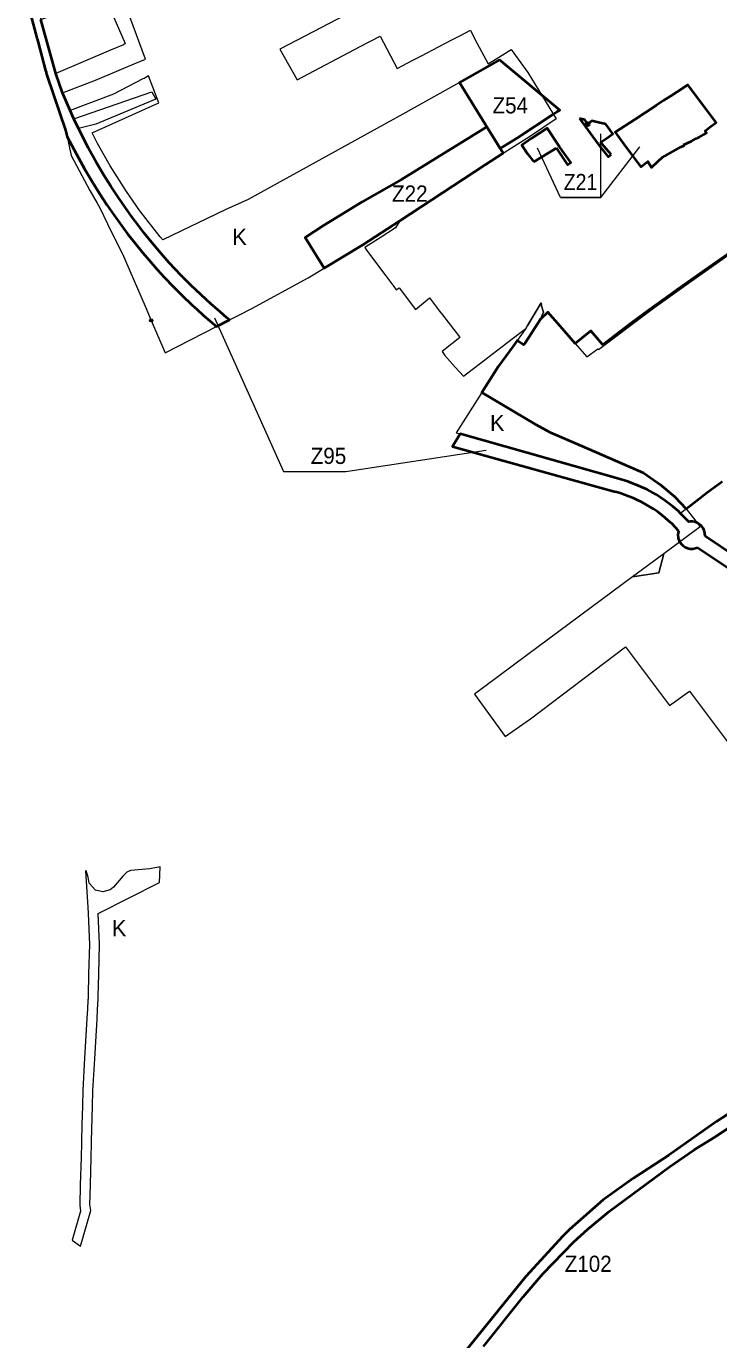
# Model space of a CAD drawing. Extents: x -650276 to -642489, y -1074425 to -1066658.
# Drawn here: x -649069 to -648043, y -1072629 to -1070685 of the extents above; entities that cross this region are included whole.
import ezdxf

# ---------------------------------------------------------------- set-up
doc = ezdxf.new("R2010")
doc.units = 0
doc.header["$LTSCALE"] = 9.6
doc.header["$PDMODE"] = 32
doc.header["$PDSIZE"] = 4.8
for name, color, linetype, lineweight in [('1', 7, 'Continuous', 13), ('42', 7, 'Continuous', 25), ('43', 7, 'Continuous', 13), ('44', 7, 'Continuous', 40), ('45', 7, 'Continuous', 40), ('46', 7, 'Continuous', 13), ('47', 7, 'Continuous', 13)]:
    doc.layers.add(name, color=color, linetype=linetype, lineweight=lineweight)

msp = doc.modelspace()

# ---------------------------------------------------------------- linework, layer by layer
at = {"layer": '1'}
for points in [[(-648597.74, -1070668.62), (-648643.953, -1070692.685), (-648693.45, -1070718.46), (-648667.72, -1070764.15), (-648574.27, -1070714.5), (-648544.862, -1070699.429), (-648519.58, -1070747.4)], [(-648519.58, -1070747.4), (-648496.18, -1070734.81), (-648484.68, -1070728.83), (-648474.03, -1070723.29), (-648466.94, -1070719.6), (-648449.19, -1070710.37), (-648438.55, -1070704.83), (-648427.9, -1070699.29), (-648410.84, -1070690.42), (-648404.45, -1070703.55), (-648384.89, -1070740.06), (-648363.96, -1070727.29), (-648350.805, -1070719.256), (-648326.033, -1070753.12), (-648309.833, -1070779.597), (-648284.021, -1070821.784), (-648322.17, -1070847.2), (-648389.33, -1070889.79), (-648515.46, -1070972.94), (-648522.01, -1070983.2), (-648543.48, -1070996.94), (-648567.23, -1071012.14), (-648564.89, -1071016.27), (-648536.41, -1071054.13), (-648524.53, -1071069.93), (-648520.86, -1071075.05), (-648516.83, -1071072.11), (-648492.65, -1071103.8), (-648475.37, -1071089.83), (-648471.64, -1071086.81), (-648456.65, -1071106.41), (-648452.32, -1071112.08), (-648427.47, -1071144.54), (-648426.82, -1071145.4), (-648452.84, -1071166.32), (-648448.82, -1071172.06), (-648433.9, -1071189.43), (-648421.16, -1071202.66), (-648416.99, -1071199.46), (-648396.21, -1071183.48), (-648379.15, -1071170.37), (-648355.66, -1071152.35), (-648347.22, -1071145.94), (-648333.1, -1071135.21), (-648328.9, -1071132.02), (-648326.92, -1071128.68), (-648306.39, -1071093.99), (-648305.83, -1071096.48), (-648306.31, -1071097.36), (-648303.08, -1071108.16), (-648307.33, -1071118.47), (-648296.34, -1071108.04), (-648278.39, -1071128.74), (-648256.04, -1071154.5), (-648238.84, -1071174.33), (-648228.01, -1071166.19), (-648222.669, -1071162.121), (-648221.672, -1071163.248), (-648140.102, -1071102.285), (-648084.716, -1071062.607), (-648029.353, -1071023.703)], [(-648305.83, -1071096.48), (-648306.39, -1071093.99), (-648326.92, -1071128.68), (-648328.9, -1071132.02), (-648341.942, -1071150.072)], [(-648303.08, -1071108.16), (-648306.31, -1071097.36), (-648305.83, -1071096.48)], [(-648330.78, -1071154.36), (-648319.77, -1071137.52), (-648307.33, -1071118.47), (-648303.08, -1071108.16)], [(-648341.942, -1071150.072), (-648332.354, -1071156.279), (-648330.78, -1071154.36)], [(-648038.18, -1071358.51), (-648060.01, -1071374.69), (-648064.98, -1071378.51), (-648071.17, -1071383.26), (-648074.27, -1071385.62), (-648091.92, -1071399.07), (-648077.53, -1071417.4), (-648070.912, -1071425.883), (-648125, -1071465.96), (-648132.14, -1071493.74), (-648170.93, -1071500), (-648326.08, -1071615.1), (-648370.52, -1071648.07), (-648405.21, -1071673.54), (-648359.48, -1071736.12), (-648321.94, -1071710.22), (-648181.6, -1071603.39), (-648116.54, -1071690.46), (-648086.68, -1071669.2), (-648027.69, -1071748)]]:
    msp.add_lwpolyline(points, dxfattribs=at)
msp.add_lwpolyline([(-648132.14, -1071493.74), (-648125, -1071465.96), (-648170.93, -1071500)], close=True, dxfattribs=at)
at = {"layer": '42'}
msp.add_lwpolyline([(-648386.587, -1070833.807), (-648512.981, -1070911.776), (-648571.14, -1070944.67), (-648628.712, -1070979.892), (-648655.76, -1070997.5), (-648627.39, -1071042.65), (-648570.23, -1071008.2), (-648515.46, -1070972.94), (-648389.33, -1070889.79), (-648362.519, -1070872.788)], close=True, dxfattribs=at)
at = {"layer": '44'}
for points in [[(-649068.65, -1070642.23), (-649054.31, -1070696.44), (-649052.77, -1070702.25), (-649052.44, -1070703.48), (-649051.03, -1070708.74), (-649040.03, -1070750.06), (-649039.38, -1070752.51), (-649039.06, -1070753.72), (-649038.51, -1070755.38), (-649027.74, -1070787.51), (-649027.64, -1070787.8), (-649019.48, -1070812.18), (-649018.48, -1070815.18), (-649011.24, -1070836.79), (-649010.67, -1070838.5), (-649007.885, -1070848.153), (-648994.464, -1070873.974), (-648982.467, -1070895.704), (-648970.712, -1070915.663), (-648960.268, -1070932.429), (-648949.389, -1070949.031), (-648939.232, -1070963.818), (-648918.601, -1070991.969), (-648896.068, -1071020.184), (-648886.874, -1071031.044), (-648874.793, -1071044.773), (-648863.847, -1071056.723), (-648851.175, -1071069.886), (-648838.696, -1071082.562), (-648823.087, -1071097.562), (-648816.379, -1071103.782), (-648806.239, -1071112.938), (-648797, -1071121), (-648790.23, -1071126.818), (-648787.207, -1071129.363), (-648767.824, -1071119.455), (-648771.725, -1071116.233), (-648781.806, -1071107.721), (-648795.407, -1071095.8), (-648824.292, -1071068.677), (-648839.273, -1071053.556), (-648856.883, -1071034.761), (-648869.629, -1071020.411), (-648880.44, -1071007.703), (-648894.164, -1070990.806), (-648902.714, -1070979.812), (-648912.396, -1070966.893), (-648922.92, -1070952.242), (-648932.78, -1070937.887), (-648943.414, -1070921.659), (-648953.605, -1070905.299), (-648965.093, -1070885.794), (-648976.834, -1070864.527), (-648985.145, -1070848.538), (-648991.386, -1070835.954), (-648998.132, -1070821.723), (-649003.641, -1070809.566), (-649014.888, -1070782.994), (-649025.129, -1070754.377), (-649047.11, -1070674.743)], [(-648079.109, -1071418.563), (-648082.391, -1071418.063), (-648085.477, -1071418.086), (-648087.928, -1071418.446), (-648100.438, -1071405.517), (-648103.268, -1071402.88), (-648111.646, -1071395.618), (-648123.313, -1071386.696), (-648136.263, -1071378.194), (-648149.571, -1071370.788), (-648162.084, -1071364.918), (-648178.158, -1071358.781), (-648191.25, -1071354.858), (-648426.18, -1071288.32), (-648437.454, -1071306.778), (-648196.236, -1071374.226)], [(-648069.022, -1071424.443), (-648074.341, -1071420.189), (-648079.108, -1071418.564), (-648079.109, -1071418.563)], [(-648063.593, -1071439.723), (-648063.862, -1071435.078), (-648064.838, -1071431.28), (-648066.623, -1071427.592), (-648069.022, -1071424.443)], [(-648103.894, -1071436.836), (-648103.478, -1071442.736), (-648101.203, -1071448.31)], [(-648101.203, -1071448.31), (-648098.259, -1071452.196), (-648096.014, -1071454.192), (-648093.059, -1071456.066), (-648089.539, -1071457.489), (-648085.585, -1071458.248), (-648081.642, -1071458.215), (-648078.539, -1071457.636), (-648074.86, -1071456.248)], [(-648016.446, -1071471.268), (-648063.593, -1071439.723)], [(-648074.86, -1071456.248), (-648027.562, -1071487.894)], [(-647942.21, -1072238.54), (-648046.69, -1072306.3), (-648117.12, -1072356), (-648169.81, -1072390.035), (-648214.73, -1072422.41), (-648264.618, -1072466.244), (-648274.53, -1072476.196), (-648328.847, -1072535.816), (-648369.37, -1072585.645), (-648431.557, -1072662.77)], [(-648391.796, -1072639.344), (-648333.178, -1072565.837), (-648303.791, -1072531.792), (-648258.165, -1072484.283), (-648237.406, -1072465.811), (-648205.298, -1072439.308), (-648116.32, -1072373.44), (-648079.76, -1072348.46), (-648050.276, -1072330.025), (-647969.894, -1072276.479)]]:
    msp.add_lwpolyline(points, dxfattribs=at)
at = {"layer": '44', "lineweight": 13}
msp.add_lwpolyline([(-648790.074, -1071116.496), (-648687.825, -1071343.817), (-648595.588, -1071343.817), (-648387.63, -1071312.498)], dxfattribs=at)
at = {"layer": '44'}
for centre, radius, start, end in [((-648244.965, -1071557.871), 190, 41.59858, 75.1393), ((-648083.781, -1071438.172), 20.157, 161.35794, 176.20098)]:
    msp.add_arc(centre, radius, start, end, dxfattribs=at)
at = {"layer": '45'}
msp.add_lwpolyline([(-648368.163, -1070734.376), (-648427.25, -1070767.95), (-648366.98, -1070865.44), (-648341.58, -1070849.98), (-648287.74, -1070814.32), (-648282.44, -1070810.84), (-648278.832, -1070808.761)], close=True, dxfattribs=at)
for points in [[(-648095.42, -1070860.3), (-648083.65, -1070854.89), (-648076.73, -1070851.07), (-648074.41, -1070849.79), (-648072.59, -1070848.79), (-648065.35, -1070844.8), (-648061.52, -1070842.68), (-648063.76, -1070839.49), (-648056.61, -1070834.26), (-648047.17, -1070827.35), (-648089.27, -1070771.57), (-648104.78, -1070781.65), (-648114.77, -1070788.08), (-648125.2, -1070794.79), (-648136.08, -1070801.79)], [(-648095.42, -1070860.3), (-648083.65, -1070854.89), (-648076.73, -1070851.07), (-648074.41, -1070849.79), (-648072.59, -1070848.79), (-648065.35, -1070844.8), (-648061.52, -1070842.68), (-648063.76, -1070839.49), (-648056.61, -1070834.26), (-648047.17, -1070827.35), (-648089.27, -1070771.57), (-648104.78, -1070781.65), (-648114.77, -1070788.08), (-648125.2, -1070794.79), (-648136.08, -1070801.79)], [(-648136.08, -1070801.79), (-648151.77, -1070812.11), (-648167.6, -1070822.53), (-648196.65, -1070841.7), (-648181.75, -1070862.74), (-648158.58, -1070892.98), (-648148.34, -1070884.92), (-648142.79, -1070893.78), (-648133.14, -1070884.6), (-648127, -1070878.75), (-648122.72, -1070876.44), (-648111.24, -1070870.11), (-648099.85, -1070863.82), (-648094.9, -1070861.09), (-648095.42, -1070860.3)], [(-648136.08, -1070801.79), (-648151.77, -1070812.11), (-648167.6, -1070822.53), (-648196.65, -1070841.7), (-648181.75, -1070862.74), (-648158.58, -1070892.98), (-648148.34, -1070884.92), (-648142.79, -1070893.78), (-648133.14, -1070884.6), (-648127, -1070878.75), (-648122.72, -1070876.44), (-648111.24, -1070870.11), (-648099.85, -1070863.82), (-648094.9, -1070861.09), (-648095.42, -1070860.3)], [(-648237.46, -1070829.68), (-648241.96, -1070823.46), (-648249.5, -1070821.08)], [(-648249.5, -1070821.08), (-648222.158, -1070859.221), (-648217.1, -1070865.56), (-648207.151, -1070878.029), (-648202.798, -1070874.754)], [(-648210.517, -1070829.445), (-648221.58, -1070827.03), (-648231.22, -1070824.92), (-648237.46, -1070829.68)], [(-648218.11, -1070856.44), (-648209.37, -1070850.44), (-648200.17, -1070844.094), (-648210.517, -1070829.445)], [(-648386.587, -1070833.807), (-648512.981, -1070911.776), (-648571.14, -1070944.67), (-648628.712, -1070979.892), (-648655.76, -1070997.5), (-648627.39, -1071042.65), (-648570.23, -1071008.2), (-648515.46, -1070972.94), (-648389.33, -1070889.79)], [(-648386.587, -1070833.807), (-648512.981, -1070911.776), (-648571.14, -1070944.67), (-648628.712, -1070979.892), (-648655.76, -1070997.5), (-648627.39, -1071042.65), (-648570.23, -1071008.2), (-648515.46, -1070972.94), (-648389.33, -1070889.79)], [(-648389.33, -1070889.79), (-648362.519, -1070872.788), (-648386.587, -1070833.807)], [(-648389.33, -1070889.79), (-648362.519, -1070872.788), (-648386.587, -1070833.807)], [(-648284.02, -1070864.91), (-648267.24, -1070889.9), (-648262.4, -1070886.58), (-648279.39, -1070862.98), (-648297.39, -1070835.36), (-648320.02, -1070850.16), (-648335.19, -1070860.49), (-648326.41, -1070873.55), (-648317.14, -1070885.48)], [(-648317.14, -1070885.48), (-648285.72, -1070865.96), (-648284.02, -1070864.91)], [(-648202.798, -1070874.754), (-648212.94, -1070862.74), (-648217.85, -1070856.93), (-648218.11, -1070856.44)], [(-647913.45, -1070940.79), (-648062.53, -1071044.59), (-648102.55, -1071072.86), (-648125.53, -1071089.51), (-648141.12, -1071100.71), (-648155.77, -1071111.23), (-648172.48, -1071123.95), (-648197.57, -1071143.03), (-648215.08, -1071156.35), (-648232.8, -1071135.6), (-648245.49, -1071145.91), (-648256.04, -1071154.5), (-648278.39, -1071128.74), (-648296.34, -1071108.04), (-648307.33, -1071118.47), (-648319.77, -1071137.52), (-648330.78, -1071154.36), (-648332.354, -1071156.279), (-648341.943, -1071150.071), (-648347.949, -1071158.385), (-648369.33, -1071188.149), (-648394.087, -1071227.18), (-648315.127, -1071274.052), (-648292.406, -1071286.112), (-648246.752, -1071306.054), (-648155.113, -1071346.082), (-648130, -1071363), (-648109, -1071381), (-648091.92, -1071399.07), (-648060.01, -1071374.69), (-648038.18, -1071358.51)]]:
    msp.add_lwpolyline(points, dxfattribs=at)
msp.add_point((-648237.46, -1070829.68), dxfattribs=at)
at = {"layer": '46'}
msp.add_line((-648217.945, -1070938.322), (-648217.945, -1070843.952), dxfattribs=at)
for points in [[(-648217.945, -1070938.322), (-648277.841, -1070938.322), (-648311.985, -1070865.23)], [(-648277.841, -1070938.322), (-648217.945, -1070938.322), (-648160.135, -1070863.066)], [(-648217.945, -1070938.322), (-648217.945, -1070938.322), (-648160.135, -1070863.066)]]:
    msp.add_lwpolyline(points, dxfattribs=at)
at = {"layer": '47'}
for p, q in [((-648883.73, -1071120.13), (-648862.97, -1071168.09)), ((-648862.97, -1071168.09), (-648787.207, -1071129.363)), ((-648191.25, -1071354.858), (-648178.158, -1071358.781))]:
    msp.add_line(p, q, dxfattribs=at)
for points in [[(-649014.888, -1070782.994), (-648966.35, -1070764.7), (-648908.94, -1070740.19), (-648892.215, -1070733.293), (-648927.2, -1070637.98), (-648941.064, -1070599.735), (-648965.569, -1070610.382), (-648956.687, -1070630.825), (-649050.081, -1070663.981), (-649047.11, -1070674.743), (-648952.455, -1070640.564), (-648922.196, -1070710.207), (-648924.668, -1070712.022), (-648943.837, -1070720.104), (-649025.129, -1070754.377)], [(-648988.248, -1072491.089), (-648973.238, -1072438.27), (-648974.424, -1072429.462), (-648973.655, -1072400.254), (-648972.605, -1072360.164), (-648972.025, -1072338.183), (-648971.955, -1072335.341), (-648970.605, -1072283.823), (-648970.001, -1072260.788), (-648967.285, -1072213.663), (-648964.865, -1072171.684), (-648963.895, -1072154.905), (-648963.052, -1072140.301), (-648962.27, -1072125.223), (-648962.165, -1072120.949), (-648961.355, -1072088.12), (-648960.263, -1072043.893), (-648962.195, -1071998.309), (-648871.27, -1071952.643), (-648870.458, -1071929.441), (-648885.56, -1071932.1), (-648914.45, -1071934.78), (-648919.79, -1071937.27), (-648925.64, -1071943.18), (-648939.51, -1071959.25), (-648944.69, -1071963.44), (-648955.25, -1071966.15), (-648966.01, -1071963.74), (-648975.65, -1071953.47), (-648976.85, -1071944.78), (-648979.85, -1071935.11), (-648980.94, -1071935.12), (-648977.48, -1071989.2), (-648976.91, -1071998.2), (-648975.27, -1072044.01), (-648976.35, -1072087.75), (-648977.16, -1072120.58), (-648977.26, -1072124.65), (-648977.3, -1072126.08), (-648977.33, -1072127.34), (-648978.03, -1072139.48), (-648978.87, -1072154.04), (-648979.84, -1072170.82), (-648982.26, -1072212.8), (-648984.99, -1072260.16), (-648985.6, -1072283.43), (-648986.31, -1072310.66), (-648986.95, -1072334.96), (-648987.02, -1072337.8), (-648987.6, -1072359.77), (-648988.65, -1072399.86), (-648989.45, -1072430.27), (-648988.27, -1072439.04), (-649000.851, -1072482.138)]]:
    msp.add_lwpolyline(points, close=True, dxfattribs=at)
for points in [[(-648971.041, -1070842.231), (-648872.375, -1070798.112), (-648874.87, -1070791.61), (-648887.84, -1070757.84), (-648894.08, -1070762.22), (-648896.11, -1070762.73), (-648939.5, -1070785.4), (-649003.641, -1070809.566), (-648998.132, -1070821.723), (-648882.919, -1070781.673), (-648876.64, -1070792.6), (-648965.475, -1070829.829), (-648991.386, -1070835.954)], [(-648386.587, -1070833.807), (-648427.25, -1070767.95), (-648511.09, -1070814.7), (-648721.54, -1070930.88), (-648740.25, -1070941.21), (-648774.23, -1070956.42), (-648866.341, -1071000.881)], [(-648787.207, -1071129.363), (-648790.23, -1071126.818), (-648797, -1071121), (-648806.239, -1071112.938), (-648816.379, -1071103.782), (-648823.087, -1071097.562), (-648838.696, -1071082.562), (-648851.175, -1071069.886), (-648863.847, -1071056.723), (-648874.793, -1071044.773), (-648886.874, -1071031.044), (-648896.068, -1071020.184), (-648918.601, -1070991.969), (-648939.232, -1070963.818), (-648949.389, -1070949.031), (-648960.268, -1070932.429), (-648970.712, -1070915.663), (-648982.467, -1070895.704), (-648994.464, -1070873.974), (-649007.885, -1070848.153), (-649003.1, -1070871.35), (-649002.82, -1070872.69), (-649002.62, -1070873.69), (-649002.15, -1070875.96), (-648974.4, -1070927.77), (-648963.5, -1070946.45), (-648959.92, -1070953.73), (-648948.29, -1070977.37), (-648924.92, -1071024.89), (-648922.98, -1071029.49), (-648921.87, -1071032.04), (-648892.82, -1071099.15), (-648883.73, -1071120.13)], [(-648991.386, -1070835.954), (-648985.145, -1070848.538), (-648976.834, -1070864.527), (-648965.093, -1070885.794), (-648953.605, -1070905.299), (-648943.414, -1070921.659), (-648932.78, -1070937.887), (-648922.92, -1070952.242), (-648912.396, -1070966.893), (-648902.714, -1070979.812), (-648894.164, -1070990.806), (-648880.44, -1071007.703), (-648869.629, -1071020.411), (-648856.883, -1071034.761), (-648839.273, -1071053.556), (-648824.292, -1071068.677)], [(-648866.341, -1071000.881), (-648870.479, -1070996.265), (-648900.337, -1070957.964), (-648920.293, -1070929.567), (-648944.376, -1070891.404), (-648963.107, -1070858.328), (-648971.041, -1070842.231)], [(-648571.14, -1070944.67), (-648512.981, -1070911.776), (-648386.587, -1070833.807)], [(-648752.967, -1071111.861), (-648734.849, -1071102.599), (-648651.375, -1071057.109), (-648627.39, -1071042.65), (-648655.76, -1070997.5), (-648634.07, -1070983.17), (-648628.712, -1070979.892), (-648571.153, -1070944.678), (-648571.14, -1070944.67)], [(-648824.292, -1071068.677), (-648795.407, -1071095.8), (-648781.806, -1071107.721), (-648771.725, -1071116.233), (-648767.824, -1071119.455), (-648752.967, -1071111.861)], [(-648130, -1071363), (-648155.113, -1071346.082), (-648246.752, -1071306.054), (-648292.406, -1071286.112), (-648315.127, -1071274.052), (-648394.104, -1071227.17), (-648432.093, -1071286.645), (-648426.18, -1071288.32), (-648191.25, -1071354.858)], [(-648178.158, -1071358.781), (-648178.158, -1071358.781), (-648162.084, -1071364.918)], [(-648162.084, -1071364.918), (-648149.571, -1071370.788), (-648136.263, -1071378.194)], [(-648136.263, -1071378.194), (-648136.263, -1071378.194), (-648123.313, -1071386.696), (-648111.646, -1071395.618), (-648103.268, -1071402.88), (-648100.438, -1071405.517), (-648091.92, -1071399.07), (-648109, -1071381), (-648130, -1071363)]]:
    msp.add_lwpolyline(points, dxfattribs=at)
msp.add_point((-648883.73, -1071120.13), dxfattribs=at)

# ---------------------------------------------------------------- texts
at = {"layer": '43'}
for p in [(-648763.558, -1071008.525), (-648763.558, -1071008.525), (-648382.039, -1071284.028), (-648941.849, -1072032.089), (-648941.849, -1072032.089)]:
    msp.add_text('K', height=24, dxfattribs=at).set_placement(p)
at = {"layer": '44', "width": 0.95}
for s, p in [('Z95', (-648647.497, -1071332.741)), ('Z102', (-648271.518, -1072529.04))]:
    msp.add_text(s, height=24, dxfattribs=at).set_placement(p)
at = {"layer": '46'}
for s, width, p in [('Z54', 0.95, (-648378.37, -1070813.706)), ('Z21', 0.9, (-648272.998, -1070927.282)), ('Z22', 0.95, (-648527.125, -1070944.357)), ('Z22', 0.95, (-648527.125, -1070944.357))]:
    msp.add_text(s, height=24, dxfattribs=dict(at, width=width)).set_placement(p)

doc.saveas('drawing.dxf')
